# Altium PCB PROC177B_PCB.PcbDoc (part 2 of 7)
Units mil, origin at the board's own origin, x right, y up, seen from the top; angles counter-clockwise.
Board outline 4257.98 x 1561.15 mil, 4 copper layers (Top Layer, Int1 (GND), Int2 (PWR), Bottom Layer), stack 63.572 mil thick; 461 components, 307 nets, 1564 pads, 607 vias.
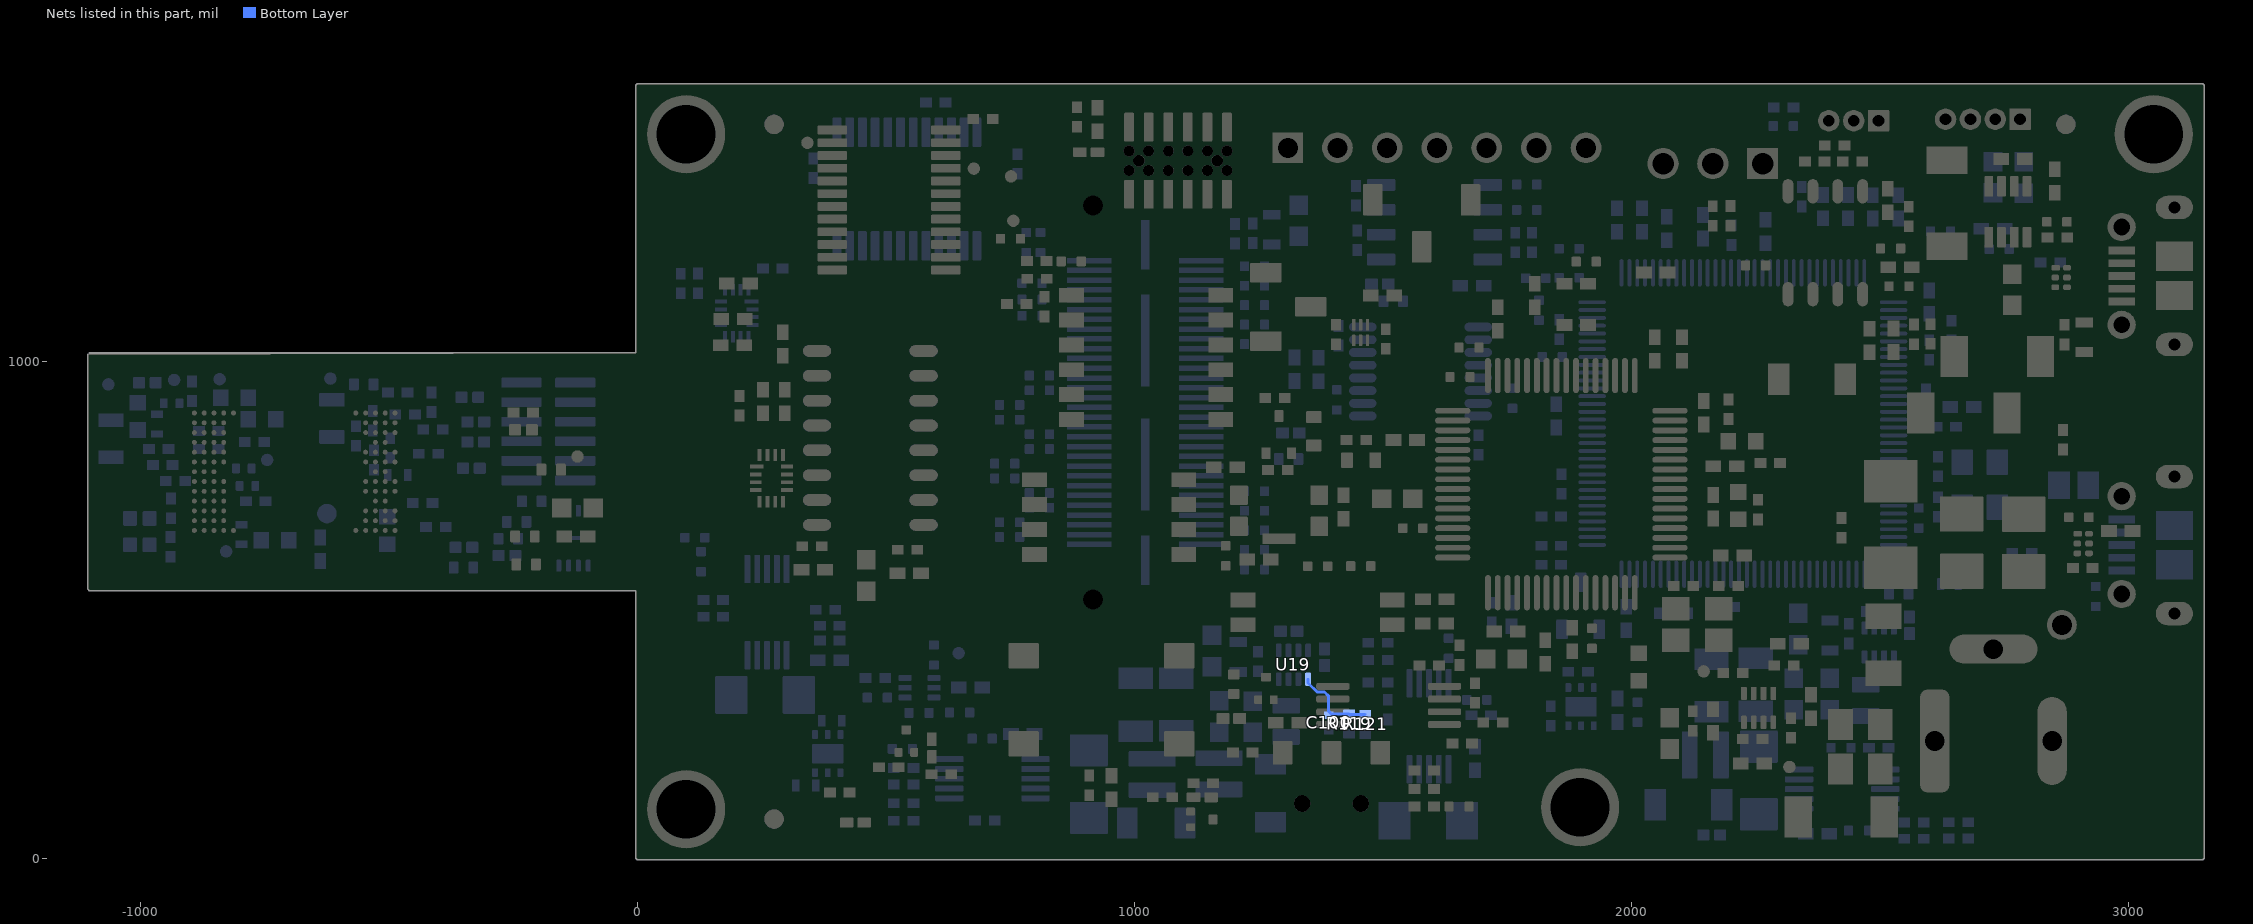
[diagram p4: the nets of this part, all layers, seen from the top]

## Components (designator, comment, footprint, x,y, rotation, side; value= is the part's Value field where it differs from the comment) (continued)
R110 "ERJ-2GE0R00X" FP-ERJ-2GE0R00X_0402-MFG 128.61,596.65 r270 bottom
R111 "ERJ-2GE0R00X" FP-ERJ-2GE0R00X_0402-MFG 694,240.6 r0 bottom
R112 "CRCW040210K0FKED" 0402L 379.03,500 r180 bottom
R113 "CRCW040210K0FKED" 0402L 387.45,437.96 r180 bottom
R114 "CRCW040210K0FKED" 0402L 153,519.6 r0 bottom
R115 "CRCW040210K0FKED" 0402L 699.53,76.05 r180 bottom
R116 "CRCW040210K0FKED" 0402L 536,181.6 r0 bottom
R117 "CRCW040210K0FKED" 0402L 536,75.6 r0 bottom
R119 "RC0402JR-070RP" FP-RC0402JR-070RP_0402-MFG 1432.18,270.17 r270 bottom
R120 "CRCW0402100KFKED" 0402 2361.22,305.27 r270 top
R121 "WR04X6802FTL" FP-WR04X6802FTL_0402-MFG 1464.61,269.17 r90 bottom
R122 "CRCW040233R2FKED" 0402 1971.24,1283.79 r90 bottom
R123 "CRCW040210K0FKED" 0402L 1405.65,1053.75 r90 top
R124 "CRCW040233R2FKED" 0402 2021.22,1283.79 r90 bottom
R125 "CRCW040233R2FKED" 0402 2071.2,1266.55 r90 bottom
R126 "CRCW040233R2FKED" 0402 2144.09,1270.37 r90 bottom
R127 "ERJ-2GE0R00X" FP-ERJ-2GE0R00X_0402-MFG 1760.74,925.16 r270 bottom
R128 "ERJ-2GE0R00X" FP-ERJ-2GE0R00X_0402-MFG 1407.48,922.09 r90 bottom
R129 "MCT06030Z0000ZP500" 0603 461,568.6 r90 top
R134 "WSL1206R0200FEB" FP-WSL1206R0200FEB_1206-MFG 1591.25,75.52 r0 bottom
R135 "CRCW040210K0FKED" 0402L 1490.17,398.71 r180 bottom
R136 "CRCW040210K0FKED" 0402L 1490.17,353.71 r180 bottom
R137 "ERJ-2GE0R00X" FP-ERJ-2GE0R00X_0402-MFG 1632.32,422.36 r90 bottom
R138 "CRCW040210K0FKED" 0402L 1505.89,1044.38 r90 top
R139 "ERJ-2GE0R00X" FP-ERJ-2GE0R00X_0402-MFG 1689,318.6 r0 bottom
R141 "ERJ-2GEJ511X" 0402L 612,169 r0 top
R142 "CRCW040210K0FKED" 0402L 1698,287.6 r180 bottom
R148 "CRCW040210K0FKED" 0402L 1490.17,433.69 r0 bottom
R150 "CRCW040210K0FKED" 0402L 1509.86,299.03 r90 bottom
R151 "ERJ-2GE0R00X" FP-ERJ-2GE0R00X_0402-MFG 566.99,292.39 r0 bottom
R152 "CRCW040210K0FKED" 0402L 87.87,1156.14 r90 bottom
R157 "CRCW040210K0FKED" 0402L 1766.32,1238.66 r270 bottom
R158 "CRCW040210K0FKED" 0402L 1800.31,1238.66 r90 bottom
R159 "ERJ-2GE0R00X" FP-ERJ-2GE0R00X_0402-MFG 1789.48,1304.1 r0 bottom
R160 "ERJ-2GE0R00X" FP-ERJ-2GE0R00X_0402-MFG 1789.48,1355.38 r0 bottom
R161 "CRCW040210K0FKED" 0402L 1448.43,1243.17 r270 bottom
R162 "CRCW040210K0FKED" 0402L 1446,1332.6 r270 bottom
R165 "CRCW040210K0FKED" 0402L 909.27,146.66 r270 top
R167 "CRCW040210K0FKED" 0402L 1721.82,273.16 r0 top
R168 "CRCW040210K0FKED" 0402L 1660,230.6 r0 top
R169 "ERJ-2GEJ101X" 0402L 2785.7,614.32 r0 bottom
R170 "ERJ-2GE0R00X" FP-ERJ-2GE0R00X_0402-MFG 2578.12,684.21 r90 bottom
R171 "ERJ-2GEJ511X" 0402L 506,182.97 r180 top
R172 "ERJ-2GEJ511X" 0402L 1288.87,781.11 r180 top
R173 "RC0402JR-070RP" FP-RC0402JR-070RP_0402-MFG 1200.25,350.14 r90 top
R174 "ERJ-2GEJ511X" 0402L 407.4,132.35 r0 top
R175 "CRCW0402100KFKEDC" FP-CRCW0402100KFKEDC_0402-IPC_B 1494.12,1155.09 r180 bottom
R176 "RC0402JR-070RP" FP-RC0402JR-070RP_0402-MFG 1520.93,1120.61 r0 bottom
R177 "CRCW0402100KFKEDC" FP-CRCW0402100KFKEDC_0402-IPC_B 1195.29,280.87 r0 top
R178 "CRCW040218K0FKEDC" FP-CRCW040218K0FKEDC_0402-IPC_B 1382.99,404.48 r90 bottom
R179 "ERJ-2GEJ511X" 0402L 1283.31,925.75 r180 top
R180 "CRCW040218K0FKEDC" FP-CRCW040218K0FKEDC_0402-IPC_B 2559.5,468.51 r90 bottom
R181 "ERJ-2GE0R00X" FP-ERJ-2GE0R00X_0402-MFG 1874.88,1226.06 r0 bottom
R184 "CRCW040210K0FKED" 0402L 1593.29,387.57 r0 top
R185 "CRCW04022K20JNED" 0402L 1685.72,332.39 r270 top
R186 "CRCW040233R2FKED" 0402 2102,1024.67 r90 top
R187 "CRCW040233R2FKED" 0402 2049.03,1178.15 r0 top
R188 "ERJ-2GE0R00X" FP-ERJ-2GE0R00X_0402-MFG 1874.9,1167.93 r0 bottom
R189 "ERJ-2GE0R00X" FP-ERJ-2GE0R00X_0402-MFG 1909.14,1200.19 r180 top
R190 "ERJ-2GE0R00X" FP-ERJ-2GE0R00X_0402-MFG 1841.07,1008.31 r0 bottom
R191 "CRCW04021K00FKED" 0402 2536.85,1310.42 r90 bottom
R192 "WSL1206R0400FEB" FP-WSL1206R0400FEB_1206-MFG 2256.59,156.6 r270 bottom
R193 "WSL1206R0400FEB" FP-WSL1206R0400FEB_1206-MFG 908.71,148.98 r90 bottom
R194 "CRCW04021K00FKED" 0402 2485.43,1310.42 r90 bottom
R195 "CRCW04021K00FKED" 0402 2436.08,1310.76 r90 bottom
R196 "CRCW04021K00FKED" 0402 2385.51,1310.76 r90 bottom
R197 "ERJ-2GE0R00X" FP-ERJ-2GE0R00X_0402-MFG 1369,587.6 r0 top
R198 "RC0402JR-070RP" FP-RC0402JR-070RP_0402-MFG 1310.49,803.03 r0 bottom
R199 "ERJ-2GE0R00X" FP-ERJ-2GE0R00X_0402-MFG 1455.55,587.64 r0 top
R200 "WSL1206R0400FEB" FP-WSL1206R0400FEB_1206-MFG 257.42,328.48 r180 bottom
R201 "CRCW0402100KFKEDC" FP-CRCW0402100KFKEDC_0402-IPC_B 1315.12,855.6 r180 bottom
R202 "CRCW040249R9FKED" 0402L 2644.1,1061.77 r90 bottom
R203 "CRCW040210K0FKED" 0402L 1583.42,139.1 r180 top
R204 "CRCW04027K87FKED" 0402L 1218.15,212.89 r180 top
R205 "CRCW040282K5FKED" 0402L 1583.42,176.6 r180 top
R206 "CRCW040210K0FKED" 0402L 763.62,1115.15 r0 top
R207 "CRCW04027K87FKED" 0402L 804.27,1165.62 r0 top
R208 "CRCW040282K5FKED" 0402L 819.66,1109.71 r90 top
R209 "CRCW040233R2FKED" 0402 1889.06,1155.5 r180 top
R213 "CRCW0402220RJNED" 0402 1420.9,706.87 r270 top
R214 "ERJ-2GE0R00X" FP-ERJ-2GE0R00X_0402-MFG 1184,608.36 r270 top
R215 "CRCW0402100KFKED" 0402 1250.68,600.84 r0 top
R216 "ERJ-2GE0R00X" FP-ERJ-2GE0R00X_0402-MFG 1673.34,1027.4 r180 top
R217 "ERJ-2GE0R00X" FP-ERJ-2GE0R00X_0402-MFG 1655.35,968.12 r180 top
R218 "CRCW040210K0FKED" 0402L 2279.59,794.95 r180 top
R219 "ERJ-2GE0R00X" FP-ERJ-2GE0R00X_0402-MFG 809.24,971.01 r180 bottom
R220 "ERJ-2GE0R00X" FP-ERJ-2GE0R00X_0402-MFG 809.24,941.33 r180 bottom
R221 "ERJ-2GE0R00X" FP-ERJ-2GE0R00X_0402-MFG 749.24,911.96 r180 bottom
R222 "ERJ-2GE0R00X" FP-ERJ-2GE0R00X_0402-MFG 749.24,882.27 r180 bottom
R223 "ERJ-2GE0R00X" FP-ERJ-2GE0R00X_0402-MFG 809.24,852.9 r180 bottom
R224 "ERJ-2GE0R00X" FP-ERJ-2GE0R00X_0402-MFG 809.24,823.22 r180 bottom
R225 "ERJ-2GE0R00X" FP-ERJ-2GE0R00X_0402-MFG 739.24,793.85 r180 bottom
R226 "ERJ-2GE0R00X" FP-ERJ-2GE0R00X_0402-MFG 739.24,764.16 r180 bottom
R227 "ERJ-2GE0R00X" FP-ERJ-2GE0R00X_0402-MFG 809.24,734.79 r180 bottom
R228 "ERJ-2GE0R00X" FP-ERJ-2GE0R00X_0402-MFG 809.24,705.11 r180 bottom
R229 "ERJ-2GE0R00X" FP-ERJ-2GE0R00X_0402-MFG 749.24,675.74 r180 bottom
R230 "ERJ-2GE0R00X" FP-ERJ-2GE0R00X_0402-MFG 749.24,646.05 r180 bottom
R231 "CRCW040210K0FKED" 0402L 2599.45,1022.42 r90 bottom
R233 "CRCW04021K00FKED" 0402 1990,482.6 r270 bottom
R234 "CRCW04024K87FKED" 0402L 2342.87,1330.76 r270 bottom
R236 "CRCW0402330KFKED" 0402L 1839,687.6 r180 bottom
R237 "CRCW04021K00FKED" 0402 2047,1024.73 r270 top
R238 "CRCW0402100KFKEDC" FP-CRCW0402100KFKEDC_0402-IPC_B 1310.78,456.59 r0 bottom
R239 "CRCW0402330KFKED" 0402L 1839,590.6 r0 bottom
R241 "ERJ-2GE0R00X" FP-ERJ-2GE0R00X_0402-MFG 2012.34,293.63 r270 bottom
R242 "ERJ-2GE0R00X" FP-ERJ-2GE0R00X_0402-MFG 1920.74,442.33 r270 top
R243 "ERJ-2GE0R00X" FP-ERJ-2GE0R00X_0402-MFG 1560.43,663.99 r180 top
R244 "CRCW0402100KFKEDC" FP-CRCW0402100KFKEDC_0402-IPC_B 2491.48,496.28 r0 bottom
R248 "CRCW040233R2FKED" 0402 1826.69,414.59 r270 top
R249 "CRCW040233R2FKED" 0402 1880.88,439.96 r270 top
R251 "CRCW040233R2FKED" 0402 1545.17,841.15 r180 top
R252 "ERJ-2GEJ511X" 0402L 1446.89,841.15 r180 top
R259 "ERJ-2GE0R00X" FP-ERJ-2GE0R00X_0402-MFG 2900.13,685.94 r180 top
R260 "CRCW040230K0FKED" 0402L 2907.98,584.07 r0 top
R261 "ERJ-2GE0R00X" FP-ERJ-2GE0R00X_0402-MFG 2934.12,526.52 r270 bottom
S1 "218-6LPST" SW_218-6LPST 1023.96,1007.62 r0 top
S2 "PTS645SM43SMTR92 LFS" SW_PTS645SM43SMT 934,318.6 r0 top
S3 "KMR243GLFG" SW_KMR243GLFG 1291.37,699 r180 top
S4 "218-4LPST" SW_218-4LPST 949.68,686.36 r0 top
S5 "218-2LPST" SW_218-2LP 1369,494.6 r0 top
SW1 "AYZ0102AGRLC" FP-AYZ0102AGRLC_SMT_SW_7MM2_5MM3-MFG 1396.77,90.3 r0 top
SW2 "JS102011JCQN" FP-JS102011JCQN_SMD3-MFG 1578.11,1277.23 r180 top locked
SW3 "CJS-1200A1" FP-CJS-1200A1_SMT3-MFG 1309.92,1109.26 r270 top
TP1 "TESTPOINT" TP_25MIL-SMT 756.73,1282.4 r180 top
TP2 "TESTPOINT" TP_25MIL-SMT 342.51,1439.28 r180 top
TP3 "TESTPOINT" TP_25MIL-SMT 752.1,1371.83 r90 top
TP4 "TESTPOINT" TP_25MIL-SMT 677.26,1387.25 r180 top
TP5 "TESTPOINT" TP_25MIL-SMT -826.71,617.3 r90 bottom
TP6 "TESTPOINT" TP_25MIL-SMT -931.35,962.11 r90 bottom
TP7 "TESTPOINT" TP_25MIL-SMT -744.31,801.31 r90 bottom
TP8 "TESTPOINT" TP_25MIL-SMT 2145.55,375.86 r180 top
TP9 "TESTPOINT" TP_25MIL-SMT 646.86,412.49 r180 bottom
TP10 "TP_SM_1MM" TP_SM_1MM -624.09,693.24 r90 bottom
TP11 "TESTPOINT" TP_VIA_060RND040 2866.07,469.33 r180 top
TP12 "TESTPOINT" TP_25MIL-SMT 2317.97,183.59 r270 top
TP13 "TESTPOINT" TP_25MIL-SMT -119.98,808.16 r90 top
TP14 "TESTPOINT" TP_25MIL-SMT -840.02,963.63 r270 bottom
TP15 "TESTPOINT" TP_25MIL-SMT -617.14,964.95 r90 bottom
TP16 "TESTPOINT" TP_25MIL-SMT -1063.83,953.21 r90 bottom
U1 "XI6432BRQAAMY" AMY0101A-MFG -688.96,777.52 r180 top locked
U2 "MX25R1635FZUIH0" USON-8L -128.06,643.83 r270 bottom
U3 "TMP112AQDRLRQ1" DRL0006A 568.08,343.01 r0 bottom
U4 "TS3A5018RSVR" RSV0016A 269.85,764.16 r0 top
U5 "TCAN1042HGVDQ1" D0008A_L 2390.27,1238.23 r90 top
U6 "INA228AIDGST" DGS0010A-MFG 2424.16,139.04 r180 bottom
U7 "INA228AIDGST" DGS0010A-MFG 261.31,495.19 r270 bottom
U8 "INA228AIDGST" DGS0010A-MFG 714.66,159.91 r0 bottom
U9 "TPD4E004DRYR" DRY0006A 2864.53,1168.25 r0 top
U10 "SN65LVDS31MDREP" D0016A_N 469.11,845.53 r0 bottom
U11 "CAT24C08WI-GT3" SOIC-8 1603.85,1279.47 r0 bottom
U12 "TS3A44159PWR" PW0016A_N 1575.81,979.08 r180 bottom
U13 "TLV75533PDRVR" DRV0006A 1898.8,304.92 r270 bottom
U14 "SN65LVDS31MDREP" D0016A_N 469.11,845.53 r180 top
U15 "TS3A27518EPWR" PW0024A-MFG 506.68,1324.13 r0 top
U16 "TPS2116DRLR" DRL0008A-MFG 2256,302.6 r90 top
U17 "SN74LVC1G11DSFR" DSF0006A 1455.43,1057.69 r90 top
U18 "TLV75533PDRVR" DRV0006A 383.33,210.5 r270 bottom
U19 "TPS6285020ADRLR" DRL0008A-MFG 1320.2,389.21 r270 bottom
U20 "TPS6285020MDRLR" DRL0008A-MFG 2498.59,433.89 r270 bottom
U21 "TM4C1294NCPDTT3" PDT0128A 2224.4,874.45 r0 bottom locked
U22 "LM4040C25QDBZR" DBZ0003A_N 1898,507.6 r90 bottom
U23 "TLIN1039DDFRQ1" DDF0008A-MFG 2757.49,1300.42 r90 top
U24 "TS3A5018RSVR" RSV0016A 200.4,1096.42 r180 bottom
U25 "INA228AIDGST" DGS0010A-MFG 1592.95,265.57 r270 bottom
U26 "93LC46B-I/ST" TSSOP-8 1511.78,307.39 r180 top
U27 "FT4232HL" LQFP64_N 1859.11,752.57 r180 top locked
U28 "TS3A27518EPWR" PW0024A-MFG 542.64,1346.19 r90 bottom
U29 "TPD4E004DRYR" DRY0006A 2908.92,633.09 r0 top
Y1 "XRCGB40M000F1S2GR0" FP-XRCGB40M000F1S2GR0_SMT_CRYSTAL_2MM0_1MM6-MFG -1000.55,656.93 r90 bottom
Y2 "ECS-160-8-33Q-RES-TR" FP-ECS-160-8-33Q-RES-TR_SMT4_3MM2_2MM5-MFG 2700.7,751.49 r270 bottom
Y3 "NX3225SA-12.000M-STD-CRS-2" NDK_NX3225SA 2132.69,470.11 r90 top
ZZ1 "This Assembly Note is for PCB labels only" AssemblyNoteLabel -760.51,4214.38 r0 top
ZZ2 "These assemblies are ESD sensitive, ESD precautions shall be observed." AssemblyNote -758.1,4136.4 r0 top
ZZ3 "These assemblies must be clean and free from flux and all contaminants. Use of no clean flux is not acceptable." AssemblyNote -758.1,4049.59 r0 top
ZZ4 "These assemblies must comply with workmanship standards IPC-A-610 Class 2, unless otherwise specified." AssemblyNote -737.53,3980.86 r0 top
ZZ5 "INDICATION FOR COMPONENTS D* ARE GIVEN AT THEIR CATHODE SIDE." AssemblyNote -736.14,3893.27 r0 top

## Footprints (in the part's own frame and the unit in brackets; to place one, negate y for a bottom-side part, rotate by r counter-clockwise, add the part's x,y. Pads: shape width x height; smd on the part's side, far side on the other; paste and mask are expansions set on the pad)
0402 [mm] "0402 from SM-752 data"
  rect 0.8x0.6 smd: 1(-0.6,0) 2(0.6,0)
  silkscreen extent -1.22,-0.52 1.22,0.52
0402_065L [mm] "0402"
  rect 0.6x0.5 smd: 1(-0.5,0) 2(0.5,0)
0402L [mm] "0402 from SM-752 data"
  rect 0.6x0.5 smd: 1(-0.5,0) 2(0.5,0)
0402S [mil] "Based on C0402S footprint from PADS legacy"
  rect 15x24 smd: 1(-20,0) 2(20,0)
0603 [mm] "0603 from SM-752 data"
  rect 1x0.95 smd: 1(-0.8,0) 2(0.8,0)
  silkscreen extent -1.52,-0.69 1.52,0.69
0603L [mm] "0603 from SM-752 data"
  rect 0.8x0.85 smd: 1(-0.7,0) 2(0.7,0)
  silkscreen extent -0.07,-0.33 0.07,0.33
0603S [mil]
  rect 20x35 smd: 1(-30,0) 2(30,0)
0805_HV [mil] "0805 with 30mil clearance between pads"
  rect 50x63 smd: 1(-40,0) 2(40,0)
  silkscreen extent -74,-40 74,40
0805L [mm] "0805 from SM-752 data"
  rect 1.1x1.4 smd: 1(-0.75,0) 2(0.75,0)
1206 [mm] "1206 from SM-752 data"
  rect 1.3x1.85 smd: 1(-1.45,0) 2(1.45,0)
  silkscreen extent -2.4,-1.21 2.4,1.21
1206_180 [mm] "1206_180"
  rect 1.1x1.6 smd: 1(-1.7,0) 2(1.7,0)
  silkscreen extent -0.9,-1 0.9,1
1206_180L [mm] "1206_180"
  rect 1.1x1.75 smd: 1(-1.35,0) 2(1.35,0)
  silkscreen extent -0.4,-0.77 0.4,0.77
3528-21 [mm] "Medium Density IPC, based on Kemet datasheet 2016-10-20"
  rrect6% 1.8x2.23 smd: 1(-1.46,0) 2(1.46,0)
  silkscreen extent -2.29,-1.5 0.76,1.5
AMY0101A-MFG [mm]
  round 0.25 smd paste+0 mask+0: A1(-5.125,3) A2(-4.625,3) A3(-4.125,3) A4(-3.625,3) A5(-3.125,3) A6(3.125,3) A7(3.625,3) A8(4.125,3) A9(4.625,3) A10(5.125,3) B1(-5.125,2.5) B2(-4.625,2.5) B3(-4.125,2.5) B4(-3.625,2.5) B7(3.625,2.5) B8(4.125,2.5) B9(4.625,2.5) B10(5.125,2.5) C1(-5.125,2) C2(-4.625,2) C3(-4.125,2) C4(-3.625,2) C7(3.625,2) C8(4.125,2) C9(4.625,2) C10(5.125,2) D2(-4.625,1.5) D3(-4.125,1.5) D7(3.625,1.5) D8(4.125,1.5) D9(4.625,1.5) D10(5.125,1.5) E1(-5.125,1) E2(-4.625,1) E3(-4.125,1) E4(-3.625,1) E7(3.625,1) E8(4.125,1) E9(4.625,1) E10(5.125,1) F1(-5.125,0.5) F2(-4.625,0.5) F3(-4.125,0.5) F4(-3.625,0.5) F7(3.625,0.5) F8(4.125,0.5) F9(4.625,0.5) F10(5.125,0.5) G2(-4.625,0) G3(-4.125,0) G8(4.125,0) G9(4.625,0) G10(5.125,0) H1(-5.125,-0.5) H2(-4.625,-0.5) H3(-4.125,-0.5) H4(-3.625,-0.5) H7(3.625,-0.5) H8(4.125,-0.5) H9(4.625,-0.5) H10(5.125,-0.5) J1(-5.125,-1) J2(-4.625,-1) J3(-4.125,-1) J4(-3.625,-1) J7(3.625,-1) J8(4.125,-1) J9(4.625,-1) J10(5.125,-1) K2(-4.625,-1.5) K3(-4.125,-1.5) K7(3.625,-1.5) K8(4.125,-1.5) K9(4.625,-1.5) K10(5.125,-1.5) L1(-5.125,-2) L2(-4.625,-2) L3(-4.125,-2) L4(-3.625,-2) L7(3.625,-2) L8(4.125,-2) L9(4.625,-2) L10(5.125,-2) M1(-5.125,-2.5) M2(-4.625,-2.5) M3(-4.125,-2.5) M4(-3.625,-2.5) M7(3.625,-2.5) M8(4.125,-2.5) M9(4.625,-2.5) M10(5.125,-2.5) N1(-5.125,-3) N2(-4.625,-3) N3(-4.125,-3) N4(-3.625,-3) N5(-3.125,-3) N6(3.125,-3) N7(3.625,-3) N8(4.125,-3) N9(4.625,-3) N10(5.125,-3)
  silkscreen extent -2.63,-3.4 2.63,3.4
APHHS1005_Green [mm] "SMD, 2-Leads, Body 1x0.5mm"
  rrect20% 0.7x0.5 smd: 1(-0.45,0) 2(0.45,0)
  silkscreen extent -0.8,-0.65 1.2,0.65
APHHS1005_Red [mm] "SMD, 2-Leads, Body 1x0.5mm"
  rrect20% 0.7x0.5 smd: 1(-0.45,0) 2(0.45,0)
  silkscreen extent 0.9,-0.31 1,0.33
AssemblyNote [mil] "Assembly Note"
AssemblyNoteLabel [mil] "Assembly Note for PCB Labels"
CE_Mark_5mm [mil] "Minimum text height for CE Mark"
CONN_105017-0001 [mm] "Molex Micro USB-B"
  rect 0.4x1.35 smd: 1(-1.3,1.35) 2(-0.65,1.35) 3(0,1.35) 4(0.65,1.35) 5(1.3,1.35)
  oval 1.2x1.9 hole 0.6 slot 1.3 at 90 deg: 6(-3.5,-1.35) 9(3.5,-1.35)
  rect 1.5x1.9 smd: 7(-1,-1.35) 8(1,-1.35)
  round 1.45 hole 0.85: 10(2.5,1.35) 11(-2.5,1.35)
  Top Layer region: 3.499,-0.399 2.299,-0.399 2.299,-2.299 3.499,-2.299
  Top Layer region: -3.5,-2.299 -2.3,-2.299 -2.3,-0.399 -3.5,-0.399
  silkscreen extent -4.1,-0.2 4.1,1.4
CUI_PJ-002AH [mm] "DC POWER JACK, R/A, TH"
  rrect50% 1.5x5.25 hole 1 square: 1(-3,0)
  oval 1.5x4.5 hole 1 square: 2(3,0)
  oval 4.5x1.5 hole 1 square: 3(0,4.7)
  silkscreen extent -4.1,-4.5 10.7,4.5
D0008A_L [mm] "SOIC, 8-Leads, Body 4.9x3.9mm, Pitch 1.27mm, IPC High Density"
  oval 1.25x0.55 smd: 1(-2.625,1.905) 2(-2.625,0.635) 3(-2.625,-0.635) 4(-2.625,-1.905) 5(2.625,-1.905) 6(2.625,-0.635) 7(2.625,0.635) 8(2.625,1.905)
  silkscreen extent -3.1,2.5 0.9,2.5
D0016A_N [mm] "SOIC, 16-Leads, Body 9.9x3.9mm, Pitch 1.27mm, IPC Medium Density"
  oval 1.45x0.6 smd: 1(-2.725,4.445) 2(-2.725,3.175) 3(-2.725,1.905) 4(-2.725,0.635) 5(-2.725,-0.635) 6(-2.725,-1.905) 7(-2.725,-3.175) 8(-2.725,-4.445) 9(2.725,-4.445) 10(2.725,-3.175) 11(2.725,-1.905) 12(2.725,-0.635) 13(2.725,0.635) 14(2.725,1.905) 15(2.725,3.175) 16(2.725,4.445)
  silkscreen extent -3.3,-5 0.9,5
DBZ0003A_N [mm] "SOT23, 3-Leads, Body 2.9x1.3mm, Pitch 0.95mm, Lead Span 2.4mm, IPC Medium Density"
  rrect17% 1x0.6 smd: 1(-1.2,0.95) 2(-1.2,-0.95) 3(1.2,0)
  silkscreen extent 0.2,-1.5 0.7,1.5
DDF0008A-MFG [mm]
  rrect22% 1.05x0.45 smd paste+0 mask+0: 1(-1.3,0.975) 2(-1.3,0.325) 3(-1.3,-0.325) 4(-1.3,-0.975) 5(1.3,-0.975) 6(1.3,-0.325) 7(1.3,0.325) 8(1.3,0.975)
  silkscreen extent -2.5,-1.48 0.4,1.48
DGS0010A-MFG [mm]
  rrect33% 1.45x0.3 smd paste+0 mask+0: 1(-2.2,1) 2(-2.2,0.5) 3(-2.2,0) 4(-2.2,-0.5) 5(-2.2,-1) 6(2.2,-1) 7(2.2,-0.5) 8(2.2,0) 9(2.2,0.5) 10(2.2,1)
  silkscreen extent -3.6,-1.55 1.05,1.55
DRL0006A [mm] "SOTFL, 6-Flat Leads, Body 1.2x1.6x0.6mm, Pitch 0.5mm, TI recommended"
  rrect33% 0.67x0.3 smd: 1(-0.74,0.5) 2(-0.74,0) 3(-0.74,-0.5) 4(0.74,-0.5) 5(0.74,0) 6(0.74,0.5)
  silkscreen extent -0.5,-0.95 0.5,-0.95
DRL0008A-MFG [mm]
  rrect33% 0.67x0.3 smd paste+0 mask+0: 1(-0.74,0.75) 2(-0.74,0.25) 3(-0.74,-0.25) 4(-0.74,-0.75) 5(0.74,-0.75) 6(0.74,-0.25) 7(0.74,0.25) 8(0.74,0.75)
  silkscreen extent -1.14,-1.28 0.65,1.57
DRV0006A [mm] "SON, 6-Leads, Body 2x2mm, Pitch 0.65mm, Thermal Pad 1.6x1mm, TI Recommended"
  rrect33% 0.45x0.3 smd: 1(-0.975,0.65) 2(-0.975,0) 3(-0.975,-0.65) 4(0.975,-0.65) 5(0.975,0) 6(0.975,0.65)
  rrect14% 1x0.7 on Bottom Paste: 7(0,-0.45) 7(0,0.45)
  rrect10% 1x1.6 smd paste-0.5: 7(0,0)
  silkscreen extent -1.05,-1.2 1.05,1.2
DRY0006A [mm] "USON-6"
  rrect67% 0.45x0.3 smd paste-0.05 mask+0: 1(-0.275,0.5)
  rrect67% 0.4x0.3 smd paste-0.05 mask+0: 2(-0.3,0) 3(-0.3,-0.5) 4(0.3,-0.5) 5(0.3,0) 6(0.3,0.5)
DSF0006A [mm] "TI recommended land pattern"
  rrect59% 0.6x0.17 smd mask+0: 1(-0.4,0.35) 2(-0.4,0) 3(-0.4,-0.35) 4(0.4,-0.35) 5(0.4,0) 6(0.4,0.35)
  silkscreen extent -0.6,-0.63 0.6,0.63
FCC_disclaimer [mil]
Fiducial10-20 [mm]
  round 1 smd mask+0: 1(0,0)
  Top Layer keep-out circle w1.178: c0,0 r0.5
FP-0022288072_HDR7-MFG [mm]
  rrect6% 1.57x1.57 hole 1.02 paste+0 mask+0: 1(-7.62,-2.925)
  round 1.57 hole 1.02 paste+0 mask+0: 2(-5.08,-2.925) 3(-2.54,-2.925) 4(0,-2.925) 5(2.54,-2.925) 6(5.08,-2.925) 7(7.62,-2.925)
  silkscreen extent -9.11,-3.05 9.02,1.27
FP-AYZ0102AGRLC_SMT_SW_7MM2_5MM3-MFG [mm]
  rrect10% 1x1.2 smd paste+0 mask+0: 1(-2.5,3.1) 2(0,3.1) 3(2.5,3.1)
  round 0.85 hole 0.85 unplated paste+0 mask+0: ""(-1.5,0.5) ""(1.5,0.5)
  silkscreen extent -3.6,-2 3.6,3.38
FP-BC050-12A-K0-0200-0160-0480-LB_HDR12-MFG [mm]
  rrect20% 0.5x2.05 smd paste+0 mask+0: 1(-2.5,-1.375) 2(-2.5,1.375) 3(-1.5,-1.375) 4(-1.5,1.375) 5(-0.5,-1.375) 6(-0.5,1.375) 7(0.5,-1.375) 8(0.5,1.375) 9(1.5,-1.375) 10(1.5,1.375) 11(2.5,-1.375) 12(2.5,1.375)
  silkscreen extent -3.17,-2.87 2.95,1.63
FP-BC084-12-A-0390-L-C_CONN_RCPT12-MFG [mm]
  rrect20% 0.5x1.47 smd paste+0 mask+0: 1(-2.5,-1.715) 2(-2.5,1.715) 3(-1.5,-1.715) 4(-1.5,1.715) 5(-0.5,-1.715) 6(-0.5,1.715) 7(0.5,-1.715) 8(0.5,1.715) 9(1.5,-1.715) 10(1.5,1.715) 11(2.5,-1.715) 12(2.5,1.715)
  round 0.56 hole 0.56 unplated paste+0 mask+0: ""(-2.5,-0.5) ""(-2.5,0.5) ""(-1.5,-0.5) ""(-1.5,0.5) ""(-0.5,-0.5) ""(-0.5,0.5) ""(0.5,-0.5) ""(0.5,0.5) ""(1.5,-0.5) ""(1.5,0.5) ""(2.5,-0.5) ""(2.5,0.5)
  round 0.6 hole 0.6 unplated paste+0 mask+0: ""(-2,0) ""(2,0)
  silkscreen extent -3.4,-3.13 3.4,1.33
FP-CJS-1200A1_SMT3-MFG [mm]
  rrect10% 1x1.6 smd paste+0 mask+0: 1(-1.75,-1.15) 2(0,1.15) 3(1.75,-1.15)
  silkscreen extent -3.46,-1.4 2.85,1.4
FP-CRCW040218K0FKEDC_0402-IPC_B [mil]
  rrect17% 25.97x22.54 smd paste+0 mask+0: 1(-16.78,0) 2(16.78,0)
  silkscreen extent -30,27 30,27
FP-CRCW040240K2FKEDC_0402-MFG [mm]
  rrect25% 0.4x0.6 smd paste+0 mask+0: 1(-0.45,0) 2(0.45,0)
  silkscreen extent -0.55,-0.67 0.55,0.67
FP-CRCW0402100KFKEDC_0402-IPC_B [mil]
  rrect17% 25.97x22.54 smd paste+0 mask+0: 1(-16.78,0) 2(16.78,0)
"FP-DFE201210U-R47M=P2_0805 (2012)-MFG" [mm]
  rrect13% 0.8x1.4 smd paste+0 mask+0: 1(-0.8,0) 2(0.8,0)
  silkscreen extent -1.2,-1.07 1.2,1.08
FP-ECS-160-8-33Q-RES-TR_SMT4_3MM2_2MM5-MFG [mm]
  rrect9% 1.3x1.1 smd paste+0 mask+0: 1(-1.15,-0.9) 2(1.15,-0.9) 3(1.15,0.9) 4(-1.15,0.9)
  silkscreen extent -1.52,-1.96 0.13,1.3
FP-ERJ-2GE0R00X_0402-MFG [mm]
  rrect21% 0.475x0.5 smd paste+0 mask+0: 1(-0.512,0) 2(0.513,0)
  silkscreen extent -0.53,0.63 0.53,0.63
FP-GJM1555C1H100FB01D_0402-MFG [mm]
  rrect25% 0.4x0.5 smd paste+0 mask+0: 1(-0.4,0) 2(0.4,0)
  silkscreen extent -0.53,-0.63 0.53,0.63
FP-GRM21BR71C475KE51L_0805-MFG [mm]
  rrect14% 0.7x1.3 smd paste+0 mask+0: 1(-0.95,0) 2(0.95,0)
  silkscreen extent -0.23,-0.7 0.23,0.7
FP-GRM31CR70J226ME19K_1206-MFG [mm]
  rrect10% 1.05x1.6 smd paste+0 mask+0: 1(-1.475,0) 2(1.475,0)
  silkscreen extent -0.58,-0.9 0.58,0.9
FP-GRM155C80J105KA12D_0402-MFG [mm]
  rrect25% 0.4x0.5 smd paste+0 mask+0: 1(-0.4,0) 2(0.4,0)
  silkscreen extent -0.5,-0.47 0.54,0.55
FP-JS102011JCQN_SMD3-MFG [mm]
  rrect10% 1x1.6 smd paste+0 mask+0: 1(-2.5,-1.2) 2(0,1.2) 3(2.5,-1.2)
  silkscreen extent -4.25,-2.67 4.25,1.8
"FP-LQM2MPZR10MJHL_0806 (2016)-MFG" [mm]
  rrect13% 0.8x2.4 smd paste-1000 mask+0: 1(-0.8,0) 2(0.8,0)
  silkscreen extent -1.1,-1.5 1.1,1.5
FP-M50-3930342_HDR3-MFG [mm]
  rrect9% 1.1x1.1 hole 0.6 paste+0 mask+0: 1(-1.27,1)
  round 1.1 hole 0.6 paste+0 mask+0: 2(0,1) 3(1.27,1)
  silkscreen extent -2.41,-0.6 2.15,1.1
FP-M50-3930442_HDR4-Recommended_Land_Pattern [mm]
  rrect9% 1.1x1.1 hole 0.6 paste+0 mask+0: 1(-1.905,1)
  round 1.1 hole 0.6 paste+0 mask+0: 2(-0.635,1) 3(0.635,1) 4(1.905,1)
FP-RC0402FR-071KL_0402-IPC_B [mil]
  rrect17% 24.23x22.54 smd paste+0 mask+0: 1(-16.87,0) 2(16.87,0)
  silkscreen extent -29,-18 29,27
FP-RC0402FR-0710KL_0402-IPC_B [mil]
  rrect17% 24.23x22.54 smd paste+0 mask+0: 1(-16.87,0) 2(16.87,0)
  silkscreen extent -29,21 29,21
FP-RC0402FR-1047K5L_0402-MFG [mm]
  rrect20% 0.5x0.6 smd paste+0 mask+0: 1(-0.5,0) 2(0.5,0)
FP-RC0402JR-070RP_0402-MFG [mm]
  rrect20% 0.5x0.6 smd paste+0 mask+0: 1(-0.5,0) 2(0.5,0)
  silkscreen extent -0.5,-0.67 0.5,0.67
FP-RT0402FRE0733R2L_0402-MFG [mm]
  rrect20% 0.5x0.6 smd paste+0 mask+0: 1(-0.5,0) 2(0.5,0)
  silkscreen extent -0.5,-0.71 0.5,0.7
FP-SSM3K35AMFV,L3F_SOT-723-MFG [mm]
  rrect25% 0.45x0.4 smd paste+0 mask+0: 1(-0.575,0.4) 2(-0.575,-0.4)
  rrect22% 0.45x0.5 smd paste+0 mask+0: 3(0.575,0)
  silkscreen extent -0.43,-0.73 0.43,0.8
FP-WR04X1003FTL_0402-IPC_B [mil]
  rrect17% 24.23x22.54 smd paste+0 mask+0: 1(-16.87,0) 2(16.87,0)
  silkscreen extent -29,-27 29,27
FP-WR04X6802FTL_0402-MFG [mm]
  rrect20% 0.5x0.6 smd paste+0 mask+0: 1(-0.5,0) 2(0.5,0)
  silkscreen extent -0.5,0.64 0.5,0.64
FP-WSL1206R0200FEB_1206-MFG [mm]
  rrect6% 1.65x1.93 smd paste+0 mask+0: 1(-1.725,0) 2(1.725,0)
  silkscreen extent -0.53,-0.93 0.53,0.93
FP-WSL1206R0400FEB_1206-MFG [mm]
  rrect6% 1.65x1.93 smd paste+0 mask+0: 1(-1.725,0) 2(1.725,0)
  silkscreen extent -0.53,-0.93 0.53,0.93
FP-XRCGB40M000F1S2GR0_SMT_CRYSTAL_2MM0_1MM6-MFG [mm]
  rrect14% 0.75x0.7 smd paste+0 mask+0: 1(-0.675,-0.5) 2(0.675,-0.5) 3(0.675,0.5) 4(-0.675,0.5)
  silkscreen extent -1.43,-1.52 1.43,0.85
LQFP64_N [mm] "Thin QFP, 64-Leads, Body 10x10mm, Pitch 0.5mm, IPC Medium Density"
  oval 1.8x0.3 smd: 1(-5.55,3.75) 2(-5.55,3.25) 3(-5.55,2.75) 4(-5.55,2.25) 5(-5.55,1.75) 6(-5.55,1.25) 7(-5.55,0.75) 8(-5.55,0.25) 9(-5.55,-0.25) 10(-5.55,-0.75) 11(-5.55,-1.25) 12(-5.55,-1.75) 13(-5.55,-2.25) 14(-5.55,-2.75) 15(-5.55,-3.25) 16(-5.55,-3.75) 33(5.55,-3.75) 34(5.55,-3.25) 35(5.55,-2.75) 36(5.55,-2.25) 37(5.55,-1.75) 38(5.55,-1.25) 39(5.55,-0.75) 40(5.55,-0.25) 41(5.55,0.25) 42(5.55,0.75) 43(5.55,1.25) 44(5.55,1.75) 45(5.55,2.25) 46(5.55,2.75) 47(5.55,3.25) 48(5.55,3.75)
  oval 0.3x1.8 smd: 17(-3.75,-5.55) 18(-3.25,-5.55) 19(-2.75,-5.55) 20(-2.25,-5.55) 21(-1.75,-5.55) 22(-1.25,-5.55) 23(-0.75,-5.55) 24(-0.25,-5.55) 25(0.25,-5.55) 26(0.75,-5.55) 27(1.25,-5.55) 28(1.75,-5.55) 29(2.25,-5.55) 30(2.75,-5.55) 31(3.25,-5.55) 32(3.75,-5.55) 49(3.75,5.55) 50(3.25,5.55) 51(2.75,5.55) 52(2.25,5.55) 53(1.75,5.55) 54(1.25,5.55) 55(0.75,5.55) 56(0.25,5.55) 57(-0.25,5.55) 58(-0.75,5.55) 59(-1.25,5.55) 60(-1.75,5.55) 61(-2.25,5.55) 62(-2.75,5.55) 63(-3.25,5.55) 64(-3.75,5.55)
  silkscreen extent -6.96,-4.25 4.25,4.25
NDK_NX3225SA [mm] "NDK"
  rect 1.2x1.4 smd: 1(-0.8,1.1) 2(-0.8,-1.1) 3(0.8,-1.1) 4(0.8,1.1)
PDT0128A [mm] "Thin QFP, 128-Leads, Body 14x14mm, Pitch 0.4mm"
  oval 1.4x0.2 smd: 1(-7.7,6.2) 2(-7.7,5.8) 3(-7.7,5.4) 4(-7.7,5) 5(-7.7,4.6) 6(-7.7,4.2) 7(-7.7,3.8) 8(-7.7,3.4) 9(-7.7,3) 10(-7.7,2.6) 11(-7.7,2.2) 12(-7.7,1.8) 13(-7.7,1.4) 14(-7.7,1) 15(-7.7,0.6) 16(-7.7,0.2) 17(-7.7,-0.2) 18(-7.7,-0.6) 19(-7.7,-1) 20(-7.7,-1.4) 21(-7.7,-1.8) 22(-7.7,-2.2) 23(-7.7,-2.6) 24(-7.7,-3) 25(-7.7,-3.4) 26(-7.7,-3.8) 27(-7.7,-4.2) 28(-7.7,-4.6) 29(-7.7,-5) 30(-7.7,-5.4) 31(-7.7,-5.8) 32(-7.7,-6.2) 65(7.7,-6.2) 66(7.7,-5.8) 67(7.7,-5.4) 68(7.7,-5) 69(7.7,-4.6) 70(7.7,-4.2) 71(7.7,-3.8) 72(7.7,-3.4) 73(7.7,-3) 74(7.7,-2.6) 75(7.7,-2.2) 76(7.7,-1.8) 77(7.7,-1.4) 78(7.7,-1) 79(7.7,-0.6) 80(7.7,-0.2) 81(7.7,0.2) 82(7.7,0.6) 83(7.7,1) 84(7.7,1.4) 85(7.7,1.8) 86(7.7,2.2) 87(7.7,2.6) 88(7.7,3) 89(7.7,3.4) 90(7.7,3.8) 91(7.7,4.2) 92(7.7,4.6) 93(7.7,5) 94(7.7,5.4) 95(7.7,5.8) 96(7.7,6.2)
  oval 0.2x1.4 smd: 33(-6.2,-7.7) 34(-5.8,-7.7) 35(-5.4,-7.7) 36(-5,-7.7) 37(-4.6,-7.7) 38(-4.2,-7.7) 39(-3.8,-7.7) 40(-3.4,-7.7) 41(-3,-7.7) 42(-2.6,-7.7) 43(-2.2,-7.7) 44(-1.8,-7.7) 45(-1.4,-7.7) 46(-1,-7.7) 47(-0.6,-7.7) 48(-0.2,-7.7) 49(0.2,-7.7) 50(0.6,-7.7) 51(1,-7.7) 52(1.4,-7.7) 53(1.8,-7.7) 54(2.2,-7.7) 55(2.6,-7.7) 56(3,-7.7) 57(3.4,-7.7) 58(3.8,-7.7) 59(4.2,-7.7) 60(4.6,-7.7) 61(5,-7.7) 62(5.4,-7.7) 63(5.8,-7.7) 64(6.2,-7.7) 97(6.2,7.7) 98(5.8,7.7) 99(5.4,7.7) 100(5,7.7) 101(4.6,7.7) 102(4.2,7.7) 103(3.8,7.7) 104(3.4,7.7) 105(3,7.7) 106(2.6,7.7) 107(2.2,7.7) 108(1.8,7.7) 109(1.4,7.7) 110(1,7.7) 111(0.6,7.7) 112(0.2,7.7) 113(-0.2,7.7) 114(-0.6,7.7) 115(-1,7.7) 116(-1.4,7.7) 117(-1.8,7.7) 118(-2.2,7.7) 119(-2.6,7.7) 120(-3,7.7) 121(-3.4,7.7) 122(-3.8,7.7) 123(-4.2,7.7) 124(-4.6,7.7) 125(-5,7.7) 126(-5.4,7.7) 127(-5.8,7.7) 128(-6.2,7.7)
  silkscreen extent -7.7,-6.3 6.3,6.99
PW0016A_N [mm] "TSOP, 16-Leads, Body 5x4.4mm, Pitch 0.65mm, IPC Medium Density"
  oval 1.4x0.45 smd: 1(-2.95,2.275) 2(-2.95,1.625) 3(-2.95,0.975) 4(-2.95,0.325) 5(-2.95,-0.325) 6(-2.95,-0.975) 7(-2.95,-1.625) 8(-2.95,-2.275) 9(2.95,-2.275) 10(2.95,-1.625) 11(2.95,-0.975) 12(2.95,-0.325) 13(2.95,0.325) 14(2.95,0.975) 15(2.95,1.625) 16(2.95,2.275)
  silkscreen extent -3.5,-2.55 1.85,2.75
PW0024A-MFG [mm]
  rrect22% 1.5x0.45 smd paste+0 mask+0: 1(-2.9,3.575) 2(-2.9,2.925) 3(-2.9,2.275) 4(-2.9,1.625) 5(-2.9,0.975) 6(-2.9,0.325) 7(-2.9,-0.325) 8(-2.9,-0.975) 9(-2.9,-1.625) 10(-2.9,-2.275) 11(-2.9,-2.925) 12(-2.9,-3.575) 13(2.9,-3.575) 14(2.9,-2.925) 15(2.9,-2.275) 16(2.9,-1.625) 17(2.9,-0.975) 18(2.9,-0.325) 19(2.9,0.325) 20(2.9,0.975) 21(2.9,1.625) 22(2.9,2.275) 23(2.9,2.925) 24(2.9,3.575)
  silkscreen extent -4.16,-3.95 1.78,3.95
RSV0016A [mm] "QFN, 16-Leads, Body 1.8x2.6mm, Pitch 0.4mm, TI Recommended"
  rect 0.7x0.2 smd: 1(-0.75,0.6)
  rect 0.6x0.2 smd: 2(-0.8,0.2) 3(-0.8,-0.2) 4(-0.8,-0.6) 9(0.8,-0.6) 10(0.8,-0.2) 11(0.8,0.2) 12(0.8,0.6)
  rect 0.2x0.6 smd: 5(-0.6,-1.2) 6(-0.2,-1.2) 7(0.2,-1.2) 8(0.6,-1.2) 13(0.6,1.2) 14(0.2,1.2) 15(-0.2,1.2) 16(-0.6,1.2)
  silkscreen extent -1.08,-1.33 1.08,1.45
Samtec_QSH-030-01-X-D-A [mm] "Receptacle, 0.5 mm, 30x2, TH"
  rect 2.27x0.279 smd: 1(-2.865,7.25) 2(2.865,7.25) 3(-2.865,6.75) 4(2.865,6.75) 5(-2.865,6.25) 6(2.865,6.25) 7(-2.865,5.75) 8(2.865,5.75) 9(-2.865,5.25) 10(2.865,5.25) 11(-2.865,4.75) 12(2.865,4.75) 13(-2.865,4.25) 14(2.865,4.25) 15(-2.865,3.75) 16(2.865,3.75) 17(-2.865,3.25) 18(2.865,3.25) 19(-2.865,2.75) 20(2.865,2.75) 21(-2.865,2.25) 22(2.865,2.25) 23(-2.865,1.75) 24(2.865,1.75) 25(-2.865,1.25) 26(2.865,1.25) 27(-2.865,0.75) 28(2.865,0.75) 29(-2.865,0.25) 30(2.865,0.25) 31(-2.865,-0.25) 32(2.865,-0.25) 33(-2.865,-0.75) 34(2.865,-0.75) 35(-2.865,-1.25) 36(2.865,-1.25) 37(-2.865,-1.75) 38(2.865,-1.75) 39(-2.865,-2.25) 40(2.865,-2.25) 41(-2.865,-2.75) 42(2.865,-2.75) 43(-2.865,-3.25) 44(2.865,-3.25) 45(-2.865,-3.75) 46(2.865,-3.75) 47(-2.865,-4.25) 48(2.865,-4.25) 49(-2.865,-4.75) 50(2.865,-4.75) 51(-2.865,-5.25) 52(2.865,-5.25) 53(-2.865,-5.75) 54(2.865,-5.75) 55(-2.865,-6.25) 56(2.865,-6.25) 57(-2.865,-6.75) 58(2.865,-6.75) 59(-2.865,-7.25) 60(2.865,-7.25)
  round 0 hole 1.02 unplated mask+0: MH1(2.67,10.065) MH2(2.67,-10.065)
  rect 0.43x2.54 smd: MP1(0,8.065) MP4(0,-8.065)
  rect 0.43x4.7 smd: MP2(0,3.175) MP3(0,-3.175)
  silkscreen extent -3.9,-10.66 3.62,10.66
SMB [mil] "Molded Diode, 2-Leads, Body 5.4x3.6mm, IPC Medium Density, based on OnSemi component dimensions"
  rect 85x107.99 smd: 1(-87.01,0) 2(87.01,0)
  silkscreen extent -155,-82 125,82
SOD-128 [mm] "SMD, 2-Leads, Body 4x2.7mm, Height 1.1mm"
  rect 1.4x2.1 smd paste-0.1: 1(-2.2,0) 2(2.2,0)
  silkscreen extent -3.45,-1.35 2.95,1.35
SOIC-8 [mm] "duplicate of SO-8.  SOIC, 8-Leads, Body 5.0x4.0mm (max), Pitch 1.27mm, IPC Medium Density"
  rrect17% 1.45x0.6 smd: 1(-2.725,1.905) 2(-2.725,0.635) 3(-2.725,-0.635) 4(-2.725,-1.905) 5(2.725,-1.905) 6(2.725,-0.635) 7(2.725,0.635) 8(2.725,1.905)
  silkscreen extent -1.37,-2.5 1.17,2.5
SOT-323 [mm] "Diodes Inc recommended land pattern.  2016-02-24"
  rrect21% 0.6x0.47 smd: 1(-0.95,0.65) 2(-0.95,-0.65) 3(0.95,0)
  silkscreen extent -1.14,-1.22 0.78,1.22
SW_218-2LP [mm] "SMD, 4-Leads, Body 3.71x5.8mm, Pitch 1.27mm"
  rect 1.27x0.76 smd: 1(-3.81,0.635) 2(-3.81,-0.635) 3(3.81,-0.635) 4(3.81,0.635)
  silkscreen extent -2.9,-1.86 2.9,2.09
SW_218-4LPST [mil] "CTS Components"
  rect 50x30 smd: 1(-150,75) 2(-150,25) 3(-150,-25) 4(-150,-75) 5(150,-75) 6(150,-25) 7(150,25) 8(150,75)
  silkscreen extent -114,-123 114,123
SW_218-6LPST [mm] "SMD, 12-Leads, Body 5.8x8.79mm"
  rect 1.27x0.76 smd: 1(-3.81,3.175) 2(-3.81,1.905) 3(-3.81,0.635) 4(-3.81,-0.635) 5(-3.81,-1.905) 6(-3.81,-3.175) 7(3.81,-3.175) 7(3.81,-3.175) 8(3.81,-1.905) 9(3.81,-0.635) 10(3.81,0.635) 11(3.81,1.905) 12(3.81,3.175)
  silkscreen extent -2.9,-4.4 2.9,4.7
SW_KMR243GLFG [mm] "SMD, 5-Leads, Body 4.2x2.8mm"
  rrect11% 0.9x1 smd: 1(-2.05,0.8) 2(2.05,0.8) 3(-2.05,-0.8) 4(2.05,-0.8)
  rrect18% 1.7x0.55 smd: 5(0,1.425)
  silkscreen extent -2.07,1.5 -1.87,1.7
SW_PTS645SM43SMT [mm] "SMD, 4-Leads, Body 6x6mm"
  rrect8% 1.55x1.3 smd: 1(-3.975,2.25) 2(3.975,2.25) 3(-3.975,-2.25) 4(3.975,-2.25)
TI_Stacked_Overlay_Small [mil]
TLMx1000_Yellow [mm] "SMD, 2-Leads, Body 1.6x0.8mm"
  rrect17% 0.6x0.8 smd: 1(-0.725,0) 2(0.725,0)
  silkscreen extent -0.98,-0.8 1.6,0.8
TP_25MIL-SMT [mil]
  round 25 smd mask+0: 1(0,0)
TP_SM_1MM [mm] "1mm Test Point, SMT"
  round 1 smd paste-0.5: 1(0,0)
TP_VIA_060RND040 [mil] "TP_VIA_060RND040"
  round 60 hole 40: 1(0,0)
TSSOP-8 [mm] "TSSOP, 8-Leads, Body 3.1x4.5mm (max), Pitch 0.65mm, IPC Medium Density"
  rrect50% 1.7x0.35 smd: 1(-2.85,0.975) 2(-2.85,0.325) 3(-2.85,-0.325) 4(-2.85,-0.975) 5(2.85,-0.975) 6(2.85,-0.325) 7(2.85,0.325) 8(2.85,0.975)
  silkscreen extent -2.4,-1.55 1.6,1.75
USON-8L [mm] "SON, 8-Leads, Body 3x2mm, Pitch 0.5mm"
  rrect40% 0.6x0.25 smd: 1(-1.4,0.75) 2(-1.4,0.25) 3(-1.4,-0.25) 4(-1.4,-0.75) 5(1.4,-0.75) 6(1.4,-0.25) 7(1.4,0.25) 8(1.4,0.75)
  rrect50% 0.2x1.6 smd: 9(0,0)
  silkscreen extent -1.55,-1.17 0.65,1.17
WEEE_Minimum [mil] "WEEElie bin"
  silkscreen extent 22,-71 54,74
Wurth_61300311021 [mm] "Header, 2.54 mm, 3x1, R/A, TH"
  rect 1.6x1.6 hole 1.1: 1(-2.54,0)
  round 1.6 hole 1.1: 2(0,0) 3(2.54,0)
  silkscreen extent -4.25,-4.04 3.81,-1.5

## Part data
C1 C100: library part CMP-0120082-1, "Multi-Layer Ceramic Capacitor 10pF C0G  ±1% 0402 Paper T/R"
C2 C37 C38 C40 C41 C94 C95 C99 C106 C113 C116 C125 C126 C138 C140 C142 C143 C144 C146 C150 C152 C153 C158: library part CMP-0078241-1, "CAP, CERM, 0.1 µF, 10 V,+/- 10%, X7R, 0402"
C3 C18 C22: library part CMP-0120013-1, "Chip Multilayer Ceramic Capacitors for General Purpose, 0402, 1.0uF, X6S, 22%, 10%, 6.3V"
C4 C5 C7 C8 C10 C11 C12 C14 C16 C19 C21 C25 C26 C28 C29 C60 C101: library part CMP-0860563-1, "CAP, CERM, 0.22 µF, 16 V,+/- 10%, X7R, 0402"
C6: library part CMP-0006298-2, "CAP, CERM, 0.047 uF, 50 V, +/- 10%, X7R, 0402"
C9 C17 C20 C69 C70: library part CMP-0006526-2, "CAP, CERM, 2.2 uF, 16 V, +/- 10%, X6S, 0402"
C13 C15 C23 C43 C44 C62 C72 C119 C120 C128 C129: library part CMP-0007295-4, "CAP, CERM, 10 uF, 10 V, +/- 20%, X6S, 0603"
C24 C27: library part CMP-0120021-1, "Chip Multilayer Ceramic Capacitors for General Purpose, 0805, 4.7uF, X7R, 15%, 10%, 16V"
C30 C45: library part CMP-0078218-1, "CAP, CERM, 0.01 µF, 16 V,+/- 10%, X7R, 0402"
C31 C34: library part CMP-0064946-2, "CAP, CERM, 0.1 uF, 50 V,+/- 10%, X7R, 0402"
C32 C33: library part CMP-0006367-2, "CAP, CERM, 4.7 pF, 50 V, +/- 2%, C0G/NP0, 0402"
C35: library part CMP-0085537-1, "CAP, CERM, 1 µF, 16 V,+/- 10%, X7R, 0603"
C36 C49 C50 C52 C53 C56 C57 C58 C59 C65 C75 C89 C91 C123 C133 C134: library part CMP-0006356-2, "CAP, CERM, 0.1 uF, 50 V, +/- 10%, X7R, AEC-Q200 Grade 1, 0402"
C39: library part CMP-0006361-2, "CAP, CERM, 4700 pF, 50 V, +/- 10%, X7R, AEC-Q200 Grade 1, 0402"
C42 C105 C124: library part CMP-0006302-2, "CAP, CERM, 2.2 uF, 10 V, +/- 10%, X7S, 0402"
C46 C47: library part CMP-0006564-3, "CAP, CERM, 10 uF, 10 V, +/- 20%, X5R, 0402"
C48 C63: library part CMP-0078216-1, "CAP, TA, 47 µF, 10 V, +/- 10%, SMD"
C51 C93 C108 C114 C127 C136 C137: library part CMP-0006272-2, "CAP, CERM, 1 uF, 10 V, +/- 10%, X6S, 0402"
C55: library part CMP-0008944-2, "CAP, CERM, 47 uF, 10 V, +/- 10%, X5R, 1206"
C61 C79: library part CMP-0092150-1, "Chip Multilayer Ceramic Capacitors for General Purpose, 1206, 22uF, X7R, 15%, 20%, 6.3V"
C66 C73: library part CMP-0007398-4, "CAP, CERM, 0.47 uF, 16 V, +/- 10%, X7R, 0603"
C67 C74: library part CMP-0006470-2, "CAP, CERM, 470 pF, 50 V, +/- 5%, C0G/NP0, 0402"
C68: library part CMP-0008940-2, "CAP, CERM, 47 uF, 6.3 V, +/- 20%, X5R, 1206"
C84 C92: library part CMP-0064967-2, "CAP, CERM, 0.47 uF, 10 V,+/- 10%, X7S, 0402"
C85: library part CMP-0078265-1, "CAP, CERM, 0.22 µF, 16 V,+/- 10%, X7R, AEC-Q200 Grade 1, 0402"
C86 C96: library part CMP-0007497-5, "CAP, CERM, 10 uF, 10 V, +/- 10%, X5R, 0603"
C88 C90 C102 C115 C118: library part CMP-0006352-2, "CAP, CERM, 0.01 uF, 25 V, +/- 10%, X7R, 0402"
C97 C98: library part CMP-0860185-1, "CAP, CERM, 8 pF, 50 V,+/- 6.25%, C0G/NP0, 0402"
C121 C122 C130 C131: library part CMP-0008676-3, "CAP, CERM, 22 uF, 10 V, +/- 20%, X6S, 1206"
C132: library part CMP-0006218-2, "CAP, CERM, 220 pF, 50 V, +/- 5%, C0G/NP0, 0402"
C135: library part CMP-0007497-5, "CAP, CERM, 10 uF, 10 V, +/- 20%, X7R, 0603"
C139 C141 C145: library part CMP-0007058-4, "CAP, CERM, 4.7 uF, 10 V, +/- 10%, X7S, 0603"
C147 C148: library part CMP-0087060-3, "Cap Ceramic 8pF 50V C0G 0.5pF SMD 0402 125C Paper T/R"
C149 C151: library part CMP-0007136-5, "CAP, CERM, 1 uF, 16 V, +/- 10%, X7R, AEC-Q200 Grade 1, 0603"
C157: library part CMP-0007995-2, "CAP, CERM, 10 uF, 16 V, +/- 10%, X7R, 0805"
D1 D2 D8 D12: library part CMP-0078758-2, "Diode, Schottky, 30 V, 2 A, AEC-Q101, SOD-128"
D3 D10: library part CMP-0078196-2, "LED, Yellow, SMD"
D4: library part CMP-0078243-3, "Diode, TVS, Uni, 5.8 V, 10.5 Vc, AEC-Q101, SMB"
D5 D6 D7: library part CMP-0067682-2, "LED, Green, SMD"
D9: library part CMP-0067681-2, "LED, Red, SMD"
F1: library part CMP-0003458-2, "Fuse, 5 A, 32VAC/VDC, SMD"
FB1 FB2: library part CMP-0003364-1, "Ferrite Bead, 30 ohm @ 100 MHz, 4 A, 0805"
FID1 FID2 FID3 FID4 FID5 FID6: library part CMP-0077181-1, "Fiducial mark.  There is nothing to buy or mount."
J1: library part CMP-0054795-1, "Header, 2.54 mm, 3x1, Gold, R/A, TH"
J2: library part CMP-0120118-1
J3: library part CMP-0087785-1, "CONN HEADER R/A 3POS 1.27MM"
J4: library part CMP-0087187-1, "CONN HDR 1.27MM R/A AU 4POS"
J5 J10: library part CMP-0055293-1, "Connector, Receptacle, Micro-USB Type B, R/A, Bottom Mount SMT"
J6: library part CMP-0075524-1, "Receptacle, 0.5 mm, 30x2, Gold, TH"
J7: library part CMP-0078270-1, "DC POWER JACK, R/A, TH"
J8: library part CMP-0049921-1
J9: library part CMP-0049930-1
L1 L5 L6: library part CMP-0095018-1, "100nH Shielded Multilayer Inductor 4A 19mOhm Max 0806 (2016 Metric)"
L2 L3 L7: library part CMP-0081523-1, "Ferrite Bead, 600 ohm @ 100 MHz, 0.3 A, 0402"
L8 L9: library part CMP-0078934-1, "Inductor, Ferrite Bead, Ferrite, 2.2 A, 0.035 ohm, AEC-Q200 Grade 1, SMD"
L14 L15: library part CMP-0092096-1, "470nH Shielded Wirewound Inductor 3A 42mOhm Max 0805 (2012 Metric)"
Logo1: library part CMP-0074838-1, "Texas Instrument Corporate Signature"
Logo2: library part CMP-0074844-1
LOGO3: library part CMP-0074847-1, "FCC_disclaimer"
Logo4: library part CMP-0074769-1
Q1 Q3 Q4: library part CMP-0091833-1, "N-Channel 20V 250mA (Ta) 500mW (Ta) Surface Mount VESM"
Q2: library part CMP-0000948-2, "MOSFET, N-CH, 100 V, 0.17 A, SOT-323"
R1 R30 R31 R32 R129: library part CMP-0025884-3, "RES, 0, 5%, 0.125 W, 0603"
R2 R5 R7 R8 R10 R12 R14 R17 R22 R23 R27 R54 R65 R71 R72 R76 R81 R82 R90 R91 R94 R97 R98 R101 R102 R103 R104 R105 R106 R107 R112 R113 R114 R115 R116 R117 R123 R135 R136 R138 R142 R148 R150 R152 R157 R158 R161 R162 R165 R167 R168 R184 R203 R206 R218 R231: library part CMP-0025958-3, "RES, 10.0 k, 1%, 0.063 W, AEC-Q200 Grade 0, 0402"
R3 R15 R18 R19 R24 R25 R26 R29 R34 R37 R38 R39 R40 R41 R42 R43 R52 R53 R55 R56 R57 R58 R59 R60 R61 R62 R63 R67 R69 R78 R80 R88 R108 R109 R110 R111 R127 R128 R137 R139 R151 R159 R160 R170 R181 R188 R189 R190 R197 R199 R214 R216 R217 R219 R220 R221 R222 R223 R224 R225 R226 R227 R228 R229 R230 R241 R242 R243 R259 R261: library part CMP-0002710-1, "0 Ohms Jumper Chip Resistor 0402 (1005 Metric) Automotive AEC-Q200 Thick Film"
R4 R9 R20 R44 R49 R75: library part CMP-0001699-1, "10 kOhms ±1% 0.063W, 1/16W Chip Resistor 0402 (1005 Metric) Moisture Resistant Thick Film"
R6 R33: library part CMP-0026938-5, "RES, 4.7 k, 5%, 0.063 W, AEC-Q200 Grade 0, 0402"
R11 R99 R120 R215: library part CMP-0025950-3, "RES, 100 k, 1%, 0.063 W, AEC-Q200 Grade 0, 0402"
R13 R16: library part CMP-0026542-2, "RES, 750, 1%, 0.063 W, AEC-Q200 Grade 0, 0402"
R21 R70 R83 R191 R194 R195 R196 R233 R237: library part CMP-0026071-3, "RES, 1.00 k, 1%, 0.063 W, AEC-Q200 Grade 0, 0402"
R28 R66 R141 R171 R172 R174 R179 R252: library part CMP-0078212-1, "RES, 510, 5%, 0.1 W, AEC-Q200 Grade 0, 0402"
R35 R77 R119 R173 R176 R198: library part CMP-0093147-1, "Res Jumper Thick Film 0402 0 Ohm 5% 1/16W Molded SMD Paper T/R"
R36: library part CMP-0120085-1, "40.2 kOhms ±1% 0.063W, 1/16W Chip Resistor 0402 (1005 Metric) Thick Film"
R45 R46 R47 R48 R51 R93: library part CMP-0120016-1, "33.2 Ohms ±1% 0.063W, 1/16W Chip Resistor 0402 (1005 Metric) Thin Film"
R50: library part CMP-0120015-1, "General Purpose Chip Resistor Thick Film 0402 47.5kOhm 1% Paper T/R"
R64 R213: library part CMP-0026878-3, "RES, 220, 5%, 0.063 W, AEC-Q200 Grade 0, 0402"
R68 R79: library part CMP-0026491-2, "RES, 61.9, 1%, 0.063 W, AEC-Q200 Grade 0, 0402"
R73 R74: library part CMP-0120018-1, "100 kOhms ±1% 0.063W, 1/16W Chip Resistor 0402 (1005 Metric) Thick Film"
R86: library part CMP-0098279-1, "RES Thick Film SMD 1kO 1% 1/16W 0402 100ppm/°C"
R121: library part CMP-0120089-1, "68 kOhms ±1% 0.063W, 1/16W Chip Resistor 0402 (1005 Metric) Thick Film"
R122 R124 R125 R126 R186 R187 R209 R248 R249 R251: library part CMP-0026299-2, "RES, 33.2, 1%, 0.063 W, AEC-Q200 Grade 0, 0402"
R134: library part CMP-0098430-1, "Res Metal Strip 1206 0.02 Ohm 1% 1/4W ±75ppm/°C Molded SMD SMD T/R"
R169: library part CMP-0026993-2, "RES, 100, 5%, 0.1 W, AEC-Q200 Grade 0, 0402"
R175 R177 R201 R238 R244: library part CMP-0092204-1, "100 kOhms ±1% 0.063W, 1/16W Chip Resistor 0402 (1005 Metric)  Thick Film"
R178 R180: library part CMP-0094741-1, "Res Thick Film 0402 18K Ohm 1% 1/16W ±100ppm/°C Molded SMD Paper T/R"
R185: library part CMP-0026890-5, "RES, 2.2 k, 5%, 0.063 W, AEC-Q200 Grade 0, 0402"
R192 R193 R200: library part CMP-0098431-1, "40 mOhms ±1% 0.25W, 1/4W Chip Resistor Automotive AEC-Q200, Current Sense, Moisture Resistant, Pulse Withstanding Metal Element"
R202: library part CMP-0026404-2, "RES, 49.9, 1%, 0.063 W, AEC-Q200 Grade 0, 0402"
R204 R207: library part CMP-0026557-2, "RES, 7.87 k, 1%, 0.063 W, AEC-Q200 Grade 0, 0402"
R205 R208: library part CMP-0026574-2, "RES, 82.5 k, 1%, 0.063 W, AEC-Q200 Grade 0, 0402"
R234: library part CMP-0026413-2, "RES, 4.87 k, 1%, 0.063 W, AEC-Q200 Grade 0, 0402"
R236 R239: library part CMP-0078210-2, "RES, 330 k, 1%, 0.063 W, AEC-Q200 Grade 0, 0402"
R260: library part CMP-0078244-2, "RES, 30.0 k, 1%, 0.063 W, AEC-Q200 Grade 0, 0402"
S1: library part CMP-0002304-1, "Switch, SPST, Slide, Off-On, 6 Pos, 0.025A, 24V, SMD"
S2: library part CMP-0079642-1, "Switch, SPST-NO, Off-Mom, 0.05 A, 12 VDC, SMD"
S3: library part CMP-0002325-1, "Switch, SPST-NO, Off-Mom, 0.01 A, 32 VDC, SMD"
S4: library part CMP-0002128-3, "Switch, Slide, SPST 4 poles, SMT"
S5: library part CMP-0002230-1, "Switch, SPST, 2 Pos, 25mA, 24VDC, SMD"
SW1: library part CMP-0096333-1, "Slide Switch SPDT Surface Mount, Right Angle"
SW2: library part CMP-0120644-1, "C & K COMPONENTS - - Schiebeschalter, Subminiatur, SPDT, Ein-Ein, Oberflächenmontage, JS Series, 300 mA"
SW3: library part CMP-0120641-1, "Slide Switch SPDT Surface Mount"
TP1 TP2 TP3 TP4 TP5 TP6 TP7 TP8 TP9 TP11 TP12 TP13 TP14 TP15 TP16: library part CMP-0078143-3, "TEST POINT.  No entry in BOM."
TP10: library part CMP-0003825-1, "1mm Test Point, SMT"
U1: library part CMP-0120794-2
U2: library part CMP-0078466-1, "ULTRA LOW POWER, 16M-BIT [x 1/x 2/x 4] CMOS MXSMIO (SERIAL MULTI I/O) FLASH MEMORY, SON-8"
U3: library part CMP-0067398-2, "Automotive Grade, 1.4V-Capable +/-0.5degC Temperature Sensor with Alert Function and I2C/SMBus, DRL0006A (SOT-OTHER-6)"
U4 U24: library part CMP-0067415-1, "10-Ohm Quad SPDT Analog Switch, RSV0016A (UQFN-16)"
U5: library part CMP-0075992-1, "Automotive Fault Protected CAN Transceiver With Flexible Data-Rate, D0008A (SOIC-8)"
U6 U7 U8 U25: library part CMP-0098432-1, "Current Sense Amplifier 1 Circuit 10-VSSOP"
U9 U29: library part CMP-0043115-3, "4-Channel ESD Protection Array for High-Speed Data Interfaces, DRY0006A (USON-6)"
U10 U14: library part CMP-0029468-1, "400 Mbps Enhanced Product Quad LVDS Transmitter with LVTTL Input and Output, 4 Tx and 0 Rx, -55 to +125 degC, 16-pin SOIC (D), Green (RoHS & no Sb/Br)"
U11: library part CMP-0005309-2, "IC, EEPROM, 8KBIT, 400KHZ, 8SOIC"
U12: library part CMP-0067412-1, "0.45-Ohm Quad SPDT Analog Switch Quad-Channel 2:1 Multiplexer/Demultiplexer with Two Controls, PW0016A (TSSOP-16)"
U13 U18: library part CMP-0013427-7, "500mA LDO, DRV0006A (WSON-6)"
U15 U28: library part CMP-0092155-1, "3.3-V, 2:1 (SPDT), 6-channel analog multiplexer with 1.8-V compatible control inputs 24-TSSOP -40 to 85"
U16: library part CMP-0088593-2, "1.6 V to 5 V, 2.5-A Low IQ Power Mux With Manual and Automatic Switchover"
U17: library part CMP-0051215-4, "Single 3-Input Positive-AND Gate, DSF0006A, LARGE T&R"
U19: library part CMP-0120067-1, "2.7-V to 6-V, 2-A Step-Down Converter in SOT583 Package"
U20: library part CMP-0120069-1, "2.7-V to 6-V, 2-A Step-Down Converter in SOT583 Package"
U21: library part CMP-0029856-2, "Tiva C Series Microcontroller, 1024 KB Flash, 256 KB SRAM, 12 Bit, 20 Channels, -40 to 105 degC, 128-Pin TQFP (PDT), Green (RoHS & no Sb/Br), Tray"
U22: library part CMP-0033001-1, "Precision Micropower Shunt Voltage Reference, 0.5% accuracy, 2.5 V, 15 ppm / degC, 15 mA, -40 to 125 degC, 3-pin SOT-23 (DBZ), Green (RoHS & no Sb/Br)"
U23: library part CMP-0090433-1, "Local Interconnect Network (LIN) Transceiver with Dominant State Timeout"
U26: library part CMP-0081524-1, "1K Microwire Compatible Serial EEPROM, TSSOP-8"
U27: library part CMP-0004747-1, "Quad High Speed USB to Multipurpose UART/MPSSE IC"
Y1: library part CMP-0120019-1, "Crystal Resonator 40MHz ±10ppm (Tol) ±20ppm (Stability) 8pF 50Ohm 4-Pin SMD T/R"
Y2: library part CMP-0095014-1, "16 MHz ±15ppm Crystal 8pF 80 Ohms 4-SMD, No Lead"
Y3: library part CMP-0081529-1, "Crystal, 12 MHz, 15 ppm, 8 pF, AEC-Q200 Grade 1, SMD"
ZZ1: library part CMP-0003616-3
ZZ2: library part CMP-0077236-1
ZZ3: library part CMP-0077237-1
ZZ4 ZZ5: library part CMP-0077238-1

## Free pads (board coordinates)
  round 157.48 hole 118.11: TH1(98.41,1456.71) TH2(1896.85,102.75) TH4(3051.18,1456.69) TH9(98.43,98.43)

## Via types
v1: diameter 18, hole 8, Top Layer to Bottom Layer, tented both sides, 603 vias
v2: diameter 19.68, hole 7.87, Top Layer to Bottom Layer, 4 vias

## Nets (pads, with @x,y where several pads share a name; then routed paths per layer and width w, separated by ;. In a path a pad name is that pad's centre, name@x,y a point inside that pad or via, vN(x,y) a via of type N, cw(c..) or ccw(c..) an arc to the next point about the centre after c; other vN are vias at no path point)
1V2_FB: C100.2 R119.1 R121.2 U19.5 | length 166.4
  Bottom Layer w5.9: U19.5@1349.73,360.08 1349.73,352.79 1368.04,334.48 1382.68,334.48 1391.2,325.97 1391.2,295.69 1397.02,289.86 R119.1@1432.18,289.86 1432.68,289.36 1464.11,289.36 R121.2@1464.61,288.86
